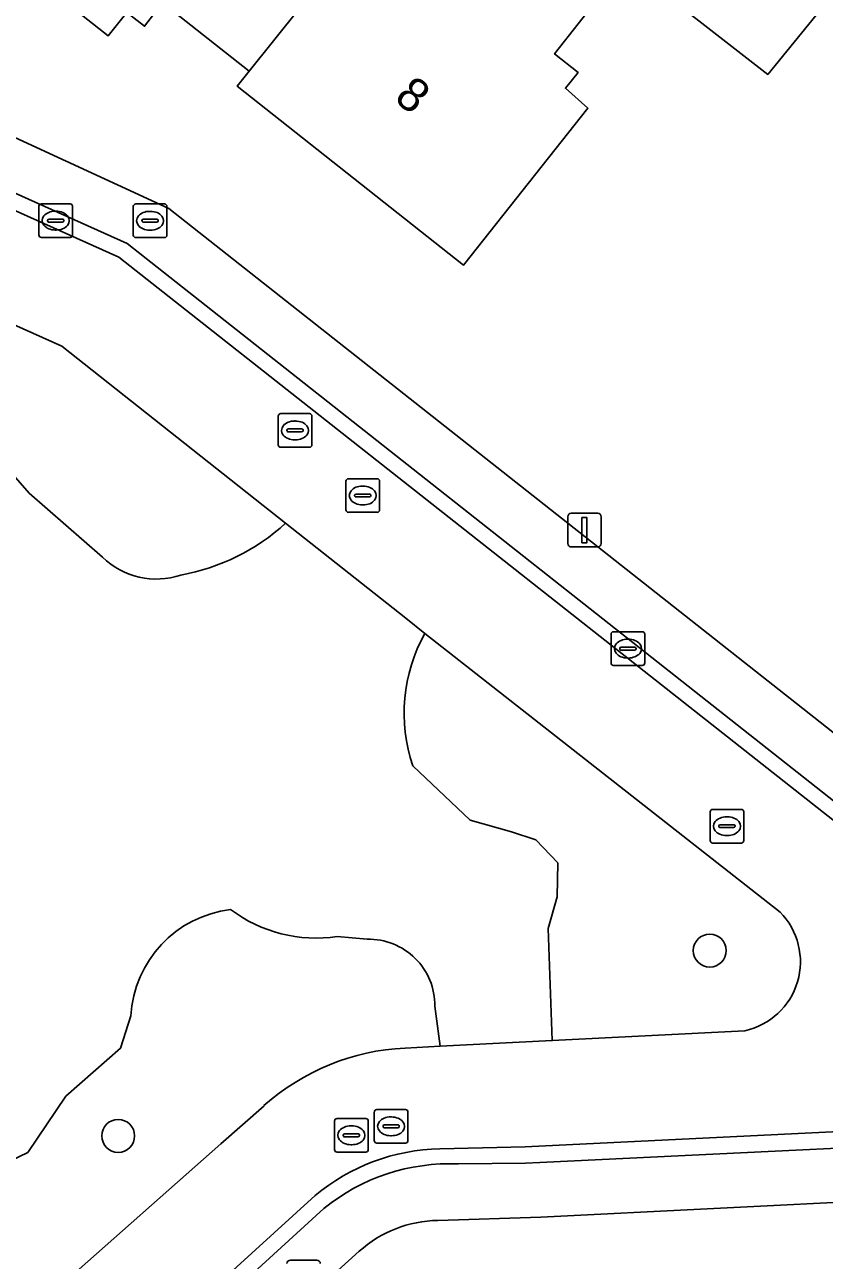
# Model space of a CAD drawing. Extents: x 162156 to 163172, y 378995 to 380779.
# Drawn here: x 162280.37 to 162304.12, y 380230.97 to 380267.71 of the extents above; entities that cross this region are included whole.
import ezdxf

# ---------------------------------------------------------------- set-up
doc = ezdxf.new("R2010")
doc.units = 0
for name, color, linetype in [('IMGEO_Boom', 7, 'Continuous'), ('IMGEO_Brandkraan', 7, 'Continuous'), ('IMGEO_Erf', 7, 'Continuous'), ('IMGEO_Groenvoorziening', 7, 'Continuous'), ('IMGEO_Kolk', 7, 'Continuous'), ('IMGEO_Lichtmast', 7, 'Continuous'), ('IMGEO_Pand', 7, 'Continuous'), ('IMGEO_Pand_nummerreeks', 7, 'Continuous'), ('IMGEO_Parkeervlak_open', 7, 'Continuous'), ('IMGEO_Rijbaan_lokaal_open', 7, 'Continuous'), ('IMGEO_Rioolput', 7, 'Continuous'), ('IMGEO_Voetpad_open', 7, 'Continuous')]:
    doc.layers.add(name, color=color, linetype=linetype)

msp = doc.modelspace()

# ---------------------------------------------------------------- linework, layer by layer
at = {"layer": 'IMGEO_Boom'}
for centre in [(162300.721, 380240.18), (162283.144, 380234.671)]:
    msp.add_circle(centre, 0.489, dxfattribs=at)
at = {"layer": 'IMGEO_Brandkraan'}
for p, q in [((162283.592, 380261.452), (162283.592, 380262.304)), ((162283.667, 380262.378), (162284.519, 380262.378)), ((162284.08, 380262.158), (162284.105, 380262.158)), ((162284.593, 380262.304), (162284.593, 380261.452)), ((162283.851, 380261.872), (162283.851, 380261.884)), ((162284.289, 380261.835), (162283.891, 380261.835)), ((162283.894, 380261.921), (162284.292, 380261.921)), ((162284.335, 380261.884), (162284.335, 380261.872)), ((162284.519, 380261.378), (162283.667, 380261.378)), ((162284.103, 380261.598), (162284.078, 380261.598))]:
    msp.add_line(p, q, dxfattribs=at)
for points in [[(162283.592, 380261.452), (162283.592, 380262.304)], [(162283.667, 380262.378), (162284.519, 380262.378)], [(162284.593, 380262.304), (162284.593, 380261.452)], [(162284.519, 380261.378), (162283.667, 380261.378)]]:
    msp.add_lwpolyline(points, dxfattribs=at)
for centre, radius, start, end in [((162283.669, 380262.302), 0.0765, 91.552, 178.448), ((162283.669, 380262.302), 0.0765, 91.552, 178.448), ((162284.517, 380262.302), 0.0765, 1.552, 88.448), ((162284.517, 380262.302), 0.0765, 1.552, 88.448), ((162283.891, 380261.881), 0.0403, 85.8775, 175.7526), ((162283.888, 380261.871), 0.0366, 178.938, 274.7102), ((162284.292, 380261.878), 0.043, 264.8664, 352.4533), ((162284.296, 380261.883), 0.0386, 1.7309, 96.639), ((162283.669, 380261.454), 0.0765, 181.552, 268.448), ((162283.669, 380261.454), 0.0765, 181.552, 268.448), ((162284.517, 380261.454), 0.0765, 271.552, 358.448), ((162284.517, 380261.454), 0.0765, 271.552, 358.448)]:
    msp.add_arc(centre, radius, start, end, dxfattribs=at)
for centre, major_axis, ratio, start_param, end_param in [((162284.079, 380261.878), (-0.387, 0.002), 0.722429, 4.712389, 7.853982), ((162284.104, 380261.878), (-0.39, 0.002), 0.717154, 1.570796, 4.712389)]:
    msp.add_ellipse(centre, major_axis=major_axis, ratio=ratio, start_param=start_param, end_param=end_param, dxfattribs=at)
at = {"layer": 'IMGEO_Erf'}
msp.add_lwpolyline([(162306.229, 380270.885), (162302.445, 380266.227), (162298.214, 380269.526), (162296.111, 380266.84), (162296.808, 380266.282), (162296.432, 380265.818), (162297.098, 380265.223), (162293.404, 380260.561), (162286.681, 380265.875), (162287.037, 380266.322), (162284.462, 380268.355), (162283.927, 380267.659), (162283.397, 380268.066), (162282.842, 380267.373), (162278.192, 380271.041), (162281.455, 380275.173), (162277.21, 380278.52), (162282.989, 380285.742), (162289.329, 380280.669), (162287.455, 380278.326), (162293.053, 380273.847), (162296.752, 380278.469)], close=True, dxfattribs=at)
for points in [[(162256.885, 380274.976), (162264.973, 380271.455), (162264.941, 380271.336), (162284.653, 380262.244), (162309.062, 380242.979), (162313.48, 380239.458)], [(162344.847, 380234.905), (162334.511, 380234.307), (162328.663, 380233.968), (162321.403, 380233.547), (162295.698, 380232.255), (162292.644, 380232.161)], [(162290.304, 380231.243), (162284.713, 380226.18)]]:
    msp.add_lwpolyline(points, dxfattribs=at)
msp.add_arc((162292.717, 380228.535), 3.627, 91.1469, 131.6941, dxfattribs=at)
at = {"layer": 'IMGEO_Groenvoorziening'}
for points in [[(162281.468, 380258.151), (162279.743, 380258.922), (162278.771, 380256.714)], [(162288.119, 380252.885), (162281.468, 380258.151)], [(162279.332, 380255.108), (162280.498, 380253.78), (162282.682, 380251.877)], [(162282.682, 380251.877), (162280.498, 380253.78), (162279.332, 380255.108)], [(162292.258, 380249.611), (162291.686, 380250.06), (162288.119, 380252.885)], [(162302.809, 380241.327), (162292.258, 380249.611)], [(162292.552, 380238.531), (162292.706, 380237.335), (162296.042, 380237.506), (162295.916, 380240.842), (162296.186, 380241.775), (162296.206, 380242.789), (162295.556, 380243.472), (162294.832, 380243.707), (162293.606, 380244.059), (162291.895, 380245.676)], [(162291.895, 380245.676), (162293.606, 380244.059), (162294.832, 380243.707), (162295.556, 380243.472), (162296.206, 380242.789), (162296.186, 380241.775), (162295.916, 380240.842), (162296.042, 380237.506), (162301.761, 380237.798)], [(162289.65, 380240.6), (162290.541, 380240.516)], [(162290.541, 380240.516), (162289.65, 380240.6)], [(162276.435, 380236.07), (162275.292, 380231.691), (162280.457, 380234.182), (162281.589, 380235.852), (162283.213, 380237.277), (162283.52, 380238.24)], [(162283.52, 380238.24), (162283.213, 380237.277), (162281.589, 380235.852), (162280.457, 380234.182), (162275.292, 380231.691)], [(162291.668, 380237.282), (162292.706, 380237.335), (162292.552, 380238.531)], [(162281.47, 380230.257), (162286.193, 380234.44), (162287.476, 380235.57)]]:
    msp.add_lwpolyline(points, dxfattribs=at)
for centre, radius, start, end in [((162283.895, 380257.509), 6.263, 280.2344, 312.4085), ((162283.895, 380257.509), 6.263, 280.2344, 312.4085), ((162284.278, 380253.509), 2.283, 225.637, 288.6437), ((162284.278, 380253.509), 2.283, 225.637, 288.6437), ((162296.498, 380247.236), 4.86, 150.7432, 198.7157), ((162296.498, 380247.236), 4.86, 150.7432, 198.7157), ((162286.888, 380238.054), 3.373, 96.8615, 176.8397), ((162286.888, 380238.054), 3.373, 96.8615, 176.8397), ((162289.014, 380244.733), 4.181, 232.7814, 278.7461), ((162289.014, 380244.733), 4.181, 232.7814, 278.7461), ((162301.312, 380239.851), 2.102, 282.3379, 44.5826), ((162290.586, 380238.55), 1.967, 359.4488, 91.2968), ((162290.586, 380238.55), 1.967, 359.4488, 91.2968), ((162291.989, 380230.507), 6.783, 92.7164, 131.7135)]:
    msp.add_arc(centre, radius, start, end, dxfattribs=at)
at = {"layer": 'IMGEO_Kolk'}
for p, q in [((162280.786, 380261.456), (162280.786, 380262.308)), ((162280.861, 380262.382), (162281.713, 380262.382)), ((162281.274, 380262.162), (162281.299, 380262.162)), ((162281.787, 380262.308), (162281.787, 380261.456)), ((162281.045, 380261.876), (162281.045, 380261.888)), ((162281.483, 380261.839), (162281.085, 380261.839)), ((162281.088, 380261.925), (162281.486, 380261.925)), ((162281.529, 380261.888), (162281.529, 380261.876)), ((162281.713, 380261.382), (162280.861, 380261.382)), ((162281.297, 380261.602), (162281.272, 380261.602)), ((162297.789, 380248.732), (162297.789, 380249.584)), ((162297.864, 380249.658), (162298.716, 380249.658)), ((162298.79, 380249.584), (162298.79, 380248.732)), ((162298.277, 380249.438), (162298.302, 380249.438)), ((162298.048, 380249.152), (162298.048, 380249.164)), ((162298.486, 380249.115), (162298.088, 380249.115)), ((162298.091, 380249.201), (162298.489, 380249.201)), ((162298.3, 380248.878), (162298.275, 380248.878)), ((162298.532, 380249.164), (162298.532, 380249.152)), ((162298.716, 380248.658), (162297.864, 380248.658))]:
    msp.add_line(p, q, dxfattribs=at)
for points in [[(162280.786, 380261.456), (162280.786, 380262.308)], [(162280.861, 380262.382), (162281.713, 380262.382)], [(162281.787, 380262.308), (162281.787, 380261.456)], [(162281.713, 380261.382), (162280.861, 380261.382)], [(162297.789, 380248.732), (162297.789, 380249.584)], [(162297.864, 380249.658), (162298.716, 380249.658)], [(162298.79, 380249.584), (162298.79, 380248.732)], [(162298.716, 380248.658), (162297.864, 380248.658)]]:
    msp.add_lwpolyline(points, dxfattribs=at)
for centre, radius, start, end in [((162280.863, 380262.306), 0.0765, 91.552, 178.448), ((162280.863, 380262.306), 0.0765, 91.552, 178.448), ((162281.711, 380262.306), 0.0765, 1.552, 88.448), ((162281.711, 380262.306), 0.0765, 1.552, 88.448), ((162281.085, 380261.885), 0.0403, 85.8775, 175.7526), ((162281.082, 380261.875), 0.0366, 178.938, 274.7102), ((162281.486, 380261.882), 0.043, 264.8664, 352.4533), ((162281.49, 380261.887), 0.0386, 1.7309, 96.639), ((162280.863, 380261.458), 0.0765, 181.552, 268.448), ((162280.863, 380261.458), 0.0765, 181.552, 268.448), ((162281.711, 380261.458), 0.0765, 271.552, 358.448), ((162281.711, 380261.458), 0.0765, 271.552, 358.448), ((162297.866, 380249.582), 0.0765, 91.552, 178.448), ((162297.866, 380249.582), 0.0765, 91.552, 178.448), ((162298.714, 380249.582), 0.0765, 1.552, 88.448), ((162298.714, 380249.582), 0.0765, 1.552, 88.448), ((162298.088, 380249.161), 0.0403, 85.8775, 175.7526), ((162298.085, 380249.151), 0.0366, 178.938, 274.7102), ((162298.489, 380249.158), 0.043, 264.8664, 352.4533), ((162298.493, 380249.163), 0.0386, 1.7309, 96.639), ((162297.866, 380248.734), 0.0765, 181.552, 268.448), ((162297.866, 380248.734), 0.0765, 181.552, 268.448), ((162298.714, 380248.734), 0.0765, 271.552, 358.448), ((162298.714, 380248.734), 0.0765, 271.552, 358.448)]:
    msp.add_arc(centre, radius, start, end, dxfattribs=at)
for centre, major_axis, ratio, start_param, end_param in [((162281.273, 380261.882), (-0.387, 0.002), 0.722429, 4.712389, 7.853982), ((162281.298, 380261.882), (-0.39, 0.002), 0.717154, 1.570796, 4.712389), ((162298.276, 380249.158), (-0.387, 0.002), 0.722429, 4.712389, 7.853982), ((162298.301, 380249.158), (-0.39, 0.002), 0.717154, 1.570796, 4.712389)]:
    msp.add_ellipse(centre, major_axis=major_axis, ratio=ratio, start_param=start_param, end_param=end_param, dxfattribs=at)
at = {"layer": 'IMGEO_Lichtmast'}
for p, q in [((162296.501, 380252.28), (162296.501, 380253.08)), ((162296.501, 380253.08), (162296.501, 380252.28)), ((162296.601, 380253.18), (162297.391, 380253.18)), ((162297.391, 380253.18), (162296.601, 380253.18)), ((162297.491, 380253.08), (162297.491, 380252.28)), ((162297.491, 380252.28), (162297.491, 380253.08)), ((162297.391, 380252.18), (162296.601, 380252.18)), ((162296.601, 380252.18), (162297.391, 380252.18)), ((162288.259, 380230.974), (162289.049, 380230.974)), ((162289.049, 380230.974), (162288.259, 380230.974))]:
    msp.add_line(p, q, dxfattribs=at)
msp.add_lwpolyline([(162296.921, 380253.055), (162297.071, 380253.055), (162297.071, 380252.305), (162296.921, 380252.305), (162296.921, 380253.055)], dxfattribs=at)
for centre, start, end in [((162296.601, 380253.08), 90, 180), ((162296.601, 380253.08), 90, 180), ((162297.391, 380253.08), 0, 90), ((162297.391, 380253.08), 360, 90), ((162296.601, 380252.28), 180, 270), ((162296.601, 380252.28), 180, 270), ((162297.391, 380252.28), 270, 0), ((162297.391, 380252.28), 270, 0), ((162288.259, 380230.874), 90, 180), ((162288.259, 380230.874), 90, 180), ((162289.049, 380230.874), 0, 90), ((162289.049, 380230.874), 360, 90)]:
    msp.add_arc(centre, 0.1, start, end, dxfattribs=at)
at = {"layer": 'IMGEO_Pand'}
for points in [[(162287.037, 380266.322), (162293.053, 380273.847), (162287.455, 380278.326), (162289.329, 380280.669), (162282.989, 380285.742), (162277.21, 380278.52), (162281.455, 380275.173), (162278.192, 380271.041), (162282.842, 380267.373), (162283.397, 380268.066), (162283.927, 380267.659), (162284.462, 380268.355)], [(162287.037, 380266.322), (162286.681, 380265.875), (162293.404, 380260.561), (162297.098, 380265.223), (162296.432, 380265.818), (162296.808, 380266.282), (162296.111, 380266.84), (162298.214, 380269.526), (162302.445, 380266.227), (162306.229, 380270.885), (162296.752, 380278.469), (162293.053, 380273.847)]]:
    msp.add_lwpolyline(points, close=True, dxfattribs=at)
at = {"layer": 'IMGEO_Parkeervlak_open'}
for points in [[(162313.48, 380239.458), (162309.062, 380242.979), (162284.653, 380262.244), (162264.941, 380271.336), (162264.973, 380271.455), (162256.885, 380274.976), (162234.564, 380284.836), (162233.962, 380283.439)], [(162233.962, 380283.439), (162283.411, 380261.197), (162307.687, 380242.035), (162311.336, 380239.172)]]:
    msp.add_lwpolyline(points, dxfattribs=at)
at = {"layer": 'IMGEO_Rijbaan_lokaal_open'}
msp.add_lwpolyline([(162233.962, 380283.439), (162233.766, 380282.994), (162283.16, 380260.799), (162307.42, 380241.672), (162311.046, 380238.809), (162311.336, 380239.172), (162307.687, 380242.035), (162283.411, 380261.197)], close=True, dxfattribs=at)
for points in [[(162283.16, 380260.799), (162233.766, 380282.994), (162233.328, 380282.059), (162232.737, 380280.664), (162232.517, 380280.173), (162250.669, 380272.072), (162261.152, 380267.394), (162265.283, 380265.541)], [(162273.787, 380261.582), (162275.582, 380260.78), (162279.743, 380258.922), (162281.468, 380258.151), (162288.119, 380252.885), (162291.686, 380250.06), (162292.258, 380249.611), (162302.809, 380241.327)], [(162311.336, 380239.172), (162311.046, 380238.809), (162307.42, 380241.672), (162283.16, 380260.799)], [(162301.761, 380237.798), (162296.042, 380237.506), (162292.706, 380237.335), (162291.668, 380237.282)], [(162346.564, 380236.852), (162295.236, 380234.347), (162292.702, 380234.286)], [(162292.702, 380234.286), (162295.236, 380234.347), (162346.564, 380236.852)], [(162295.241, 380233.863), (162295.669, 380233.884), (162328.568, 380235.47), (162334.411, 380235.752), (162346.317, 380236.325)], [(162287.476, 380235.57), (162286.193, 380234.44), (162281.47, 380230.257)], [(162293.252, 380233.837), (162295.241, 380233.863)], [(162289.001, 380232.898), (162283.128, 380227.55)], [(162283.128, 380227.55), (162289.001, 380232.898)], [(162283.613, 380227.351), (162289.253, 380232.511)]]:
    msp.add_lwpolyline(points, dxfattribs=at)
for centre, radius, start, end in [((162301.312, 380239.851), 2.102, 282.3379, 44.5826), ((162291.989, 380230.507), 6.783, 92.7164, 131.7135), ((162292.811, 380228.367), 5.92, 91.0558, 130.0597), ((162292.811, 380228.367), 5.92, 91.0558, 130.0597), ((162292.994, 380227.923), 5.92, 87.4984, 129.1908)]:
    msp.add_arc(centre, radius, start, end, dxfattribs=at)
at = {"layer": 'IMGEO_Rioolput'}
for p, q in [((162287.898, 380255.219), (162287.898, 380256.071)), ((162287.973, 380256.145), (162288.825, 380256.145)), ((162288.386, 380255.925), (162288.411, 380255.925)), ((162288.899, 380256.071), (162288.899, 380255.219)), ((162288.157, 380255.639), (162288.157, 380255.651)), ((162288.595, 380255.602), (162288.197, 380255.602)), ((162288.2, 380255.688), (162288.598, 380255.688)), ((162288.641, 380255.651), (162288.641, 380255.639)), ((162288.825, 380255.145), (162287.973, 380255.145)), ((162288.409, 380255.365), (162288.384, 380255.365)), ((162289.91, 380253.284), (162289.91, 380254.136)), ((162289.985, 380254.21), (162290.837, 380254.21)), ((162290.398, 380253.99), (162290.423, 380253.99)), ((162290.911, 380254.136), (162290.911, 380253.284)), ((162290.169, 380253.704), (162290.169, 380253.716)), ((162290.607, 380253.667), (162290.209, 380253.667)), ((162290.212, 380253.753), (162290.61, 380253.753)), ((162290.653, 380253.716), (162290.653, 380253.704)), ((162290.421, 380253.43), (162290.396, 380253.43)), ((162290.837, 380253.21), (162289.985, 380253.21)), ((162300.732, 380243.453), (162300.732, 380244.305)), ((162300.807, 380244.379), (162301.659, 380244.379)), ((162301.22, 380244.159), (162301.245, 380244.159)), ((162301.733, 380244.305), (162301.733, 380243.453)), ((162300.991, 380243.873), (162300.991, 380243.885)), ((162301.429, 380243.836), (162301.031, 380243.836)), ((162301.034, 380243.922), (162301.432, 380243.922)), ((162301.475, 380243.885), (162301.475, 380243.873)), ((162301.659, 380243.379), (162300.807, 380243.379)), ((162301.243, 380243.599), (162301.218, 380243.599)), ((162290.753, 380234.53), (162290.753, 380235.382)), ((162290.828, 380235.456), (162291.68, 380235.456)), ((162291.754, 380235.382), (162291.754, 380234.53)), ((162289.571, 380234.263), (162289.571, 380235.115)), ((162289.646, 380235.189), (162290.498, 380235.189)), ((162290.059, 380234.969), (162290.084, 380234.969)), ((162290.572, 380235.115), (162290.572, 380234.263)), ((162291.012, 380234.95), (162291.012, 380234.962)), ((162291.45, 380234.913), (162291.052, 380234.913)), ((162291.055, 380234.999), (162291.453, 380234.999)), ((162291.241, 380235.236), (162291.266, 380235.236)), ((162291.496, 380234.962), (162291.496, 380234.95)), ((162289.83, 380234.683), (162289.83, 380234.695)), ((162290.268, 380234.646), (162289.87, 380234.646)), ((162289.873, 380234.732), (162290.271, 380234.732)), ((162290.314, 380234.695), (162290.314, 380234.683)), ((162291.264, 380234.676), (162291.239, 380234.676)), ((162290.498, 380234.189), (162289.646, 380234.189)), ((162290.082, 380234.409), (162290.057, 380234.409)), ((162291.68, 380234.456), (162290.828, 380234.456))]:
    msp.add_line(p, q, dxfattribs=at)
for points in [[(162287.898, 380255.219), (162287.898, 380256.071)], [(162287.973, 380256.145), (162288.825, 380256.145)], [(162288.899, 380256.071), (162288.899, 380255.219)], [(162288.825, 380255.145), (162287.973, 380255.145)], [(162289.91, 380253.284), (162289.91, 380254.136)], [(162289.985, 380254.21), (162290.837, 380254.21)], [(162290.911, 380254.136), (162290.911, 380253.284)], [(162290.837, 380253.21), (162289.985, 380253.21)], [(162300.732, 380243.453), (162300.732, 380244.305)], [(162300.807, 380244.379), (162301.659, 380244.379)], [(162301.733, 380244.305), (162301.733, 380243.453)], [(162301.659, 380243.379), (162300.807, 380243.379)], [(162290.753, 380234.53), (162290.753, 380235.382)], [(162290.828, 380235.456), (162291.68, 380235.456)], [(162291.754, 380235.382), (162291.754, 380234.53)], [(162289.571, 380234.263), (162289.571, 380235.115)], [(162289.646, 380235.189), (162290.498, 380235.189)], [(162290.572, 380235.115), (162290.572, 380234.263)], [(162290.498, 380234.189), (162289.646, 380234.189)], [(162291.68, 380234.456), (162290.828, 380234.456)]]:
    msp.add_lwpolyline(points, dxfattribs=at)
for centre, radius, start, end in [((162287.975, 380256.069), 0.0765, 91.552, 178.448), ((162287.975, 380256.069), 0.0765, 91.552, 178.448), ((162288.823, 380256.069), 0.0765, 1.552, 88.448), ((162288.823, 380256.069), 0.0765, 1.552, 88.448), ((162288.197, 380255.648), 0.0403, 85.8775, 175.7526), ((162288.194, 380255.638), 0.0366, 178.938, 274.7102), ((162288.598, 380255.645), 0.043, 264.8664, 352.4533), ((162288.602, 380255.65), 0.0386, 1.7309, 96.639), ((162287.975, 380255.221), 0.0765, 181.552, 268.448), ((162287.975, 380255.221), 0.0765, 181.552, 268.448), ((162288.823, 380255.221), 0.0765, 271.552, 358.448), ((162288.823, 380255.221), 0.0765, 271.552, 358.448), ((162289.987, 380254.134), 0.0765, 91.552, 178.448), ((162289.987, 380254.134), 0.0765, 91.552, 178.448), ((162290.835, 380254.134), 0.0765, 1.552, 88.448), ((162290.835, 380254.134), 0.0765, 1.552, 88.448), ((162290.209, 380253.713), 0.0403, 85.8775, 175.7526), ((162290.206, 380253.703), 0.0366, 178.938, 274.7102), ((162290.61, 380253.71), 0.043, 264.8664, 352.4533), ((162290.614, 380253.715), 0.0386, 1.7309, 96.639), ((162289.987, 380253.286), 0.0765, 181.552, 268.448), ((162289.987, 380253.286), 0.0765, 181.552, 268.448), ((162290.835, 380253.286), 0.0765, 271.552, 358.448), ((162290.835, 380253.286), 0.0765, 271.552, 358.448), ((162300.809, 380244.303), 0.0765, 91.552, 178.448), ((162300.809, 380244.303), 0.0765, 91.552, 178.448), ((162301.657, 380244.303), 0.0765, 1.552, 88.448), ((162301.657, 380244.303), 0.0765, 1.552, 88.448), ((162301.031, 380243.882), 0.0403, 85.8775, 175.7526), ((162301.028, 380243.872), 0.0366, 178.938, 274.7102), ((162301.432, 380243.879), 0.043, 264.8664, 352.4533), ((162301.436, 380243.884), 0.0386, 1.7309, 96.639), ((162300.809, 380243.455), 0.0765, 181.552, 268.448), ((162300.809, 380243.455), 0.0765, 181.552, 268.448), ((162301.657, 380243.455), 0.0765, 271.552, 358.448), ((162301.657, 380243.455), 0.0765, 271.552, 358.448), ((162290.83, 380235.38), 0.0765, 91.552, 178.448), ((162290.83, 380235.38), 0.0765, 91.552, 178.448), ((162291.678, 380235.38), 0.0765, 1.552, 88.448), ((162291.678, 380235.38), 0.0765, 1.552, 88.448), ((162289.648, 380235.113), 0.0765, 91.552, 178.448), ((162289.648, 380235.113), 0.0765, 91.552, 178.448), ((162290.496, 380235.113), 0.0765, 1.552, 88.448), ((162290.496, 380235.113), 0.0765, 1.552, 88.448), ((162291.052, 380234.959), 0.0403, 85.8775, 175.7526), ((162291.049, 380234.949), 0.0366, 178.938, 274.7102), ((162291.453, 380234.956), 0.043, 264.8664, 352.4533), ((162291.457, 380234.961), 0.0386, 1.7309, 96.639), ((162289.87, 380234.692), 0.0403, 85.8775, 175.7526), ((162289.867, 380234.682), 0.0366, 178.938, 274.7102), ((162290.271, 380234.689), 0.043, 264.8664, 352.4533), ((162290.275, 380234.694), 0.0386, 1.7309, 96.639), ((162290.83, 380234.532), 0.0765, 181.552, 268.448), ((162290.83, 380234.532), 0.0765, 181.552, 268.448), ((162291.678, 380234.532), 0.0765, 271.552, 358.448), ((162291.678, 380234.532), 0.0765, 271.552, 358.448), ((162289.648, 380234.265), 0.0765, 181.552, 268.448), ((162289.648, 380234.265), 0.0765, 181.552, 268.448), ((162290.496, 380234.265), 0.0765, 271.552, 358.448), ((162290.496, 380234.265), 0.0765, 271.552, 358.448)]:
    msp.add_arc(centre, radius, start, end, dxfattribs=at)
for centre, major_axis, ratio, start_param, end_param in [((162288.385, 380255.645), (-0.387, 0.002), 0.722429, 4.712389, 7.853982), ((162288.41, 380255.645), (-0.39, 0.002), 0.717154, 1.570796, 4.712389), ((162290.397, 380253.71), (-0.387, 0.002), 0.722429, 4.712389, 7.853982), ((162290.422, 380253.71), (-0.39, 0.002), 0.717154, 1.570796, 4.712389), ((162301.219, 380243.879), (-0.387, 0.002), 0.722429, 4.712389, 7.853982), ((162301.244, 380243.879), (-0.39, 0.002), 0.717154, 1.570796, 4.712389), ((162290.058, 380234.689), (-0.387, 0.002), 0.722429, 4.712389, 7.853982), ((162290.083, 380234.689), (-0.39, 0.002), 0.717154, 1.570796, 4.712389), ((162291.24, 380234.956), (-0.387, 0.002), 0.722429, 4.712389, 7.853982), ((162291.265, 380234.956), (-0.39, 0.002), 0.717154, 1.570796, 4.712389)]:
    msp.add_ellipse(centre, major_axis=major_axis, ratio=ratio, start_param=start_param, end_param=end_param, dxfattribs=at)
at = {"layer": 'IMGEO_Voetpad_open'}
for points in [[(162328.663, 380233.968), (162328.568, 380235.47), (162295.669, 380233.884), (162295.241, 380233.863), (162293.252, 380233.837)], [(162292.644, 380232.161), (162295.698, 380232.255), (162321.403, 380233.547), (162328.663, 380233.968)], [(162289.253, 380232.511), (162283.613, 380227.351)], [(162284.713, 380226.18), (162290.304, 380231.243)]]:
    msp.add_lwpolyline(points, dxfattribs=at)
for centre, radius, start, end in [((162292.994, 380227.923), 5.92, 87.4984, 129.1908), ((162292.717, 380228.535), 3.627, 91.1469, 131.6941)]:
    msp.add_arc(centre, radius, start, end, dxfattribs=at)

# ---------------------------------------------------------------- texts
at = {"layer": 'IMGEO_Pand_nummerreeks'}
msp.add_text('8', height=1, rotation=321.6534, dxfattribs=at).set_placement((162291.307, 380265.463))

doc.saveas('drawing.dxf')
